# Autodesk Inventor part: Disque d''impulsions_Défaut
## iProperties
Shininess: 64.0
Length Units: 11269
Angle Units: 11279
Time Units: 11290
Mass Units: 11283
Length Display Precision: 3
Angle Display Precision: 2
Compacted: True
Part Number: Disque d''impulsions_Défaut
Document SubType Name: Modeling
Created: 2006-01
Material: Par défaut
Designer: riri
Density: 0.0
Volumn: 0.0
Area: 0.0
PropertySet Name: Model Information
Control State: 0
Master: False
Checked Out: False
Author: riri
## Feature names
1. Base1
